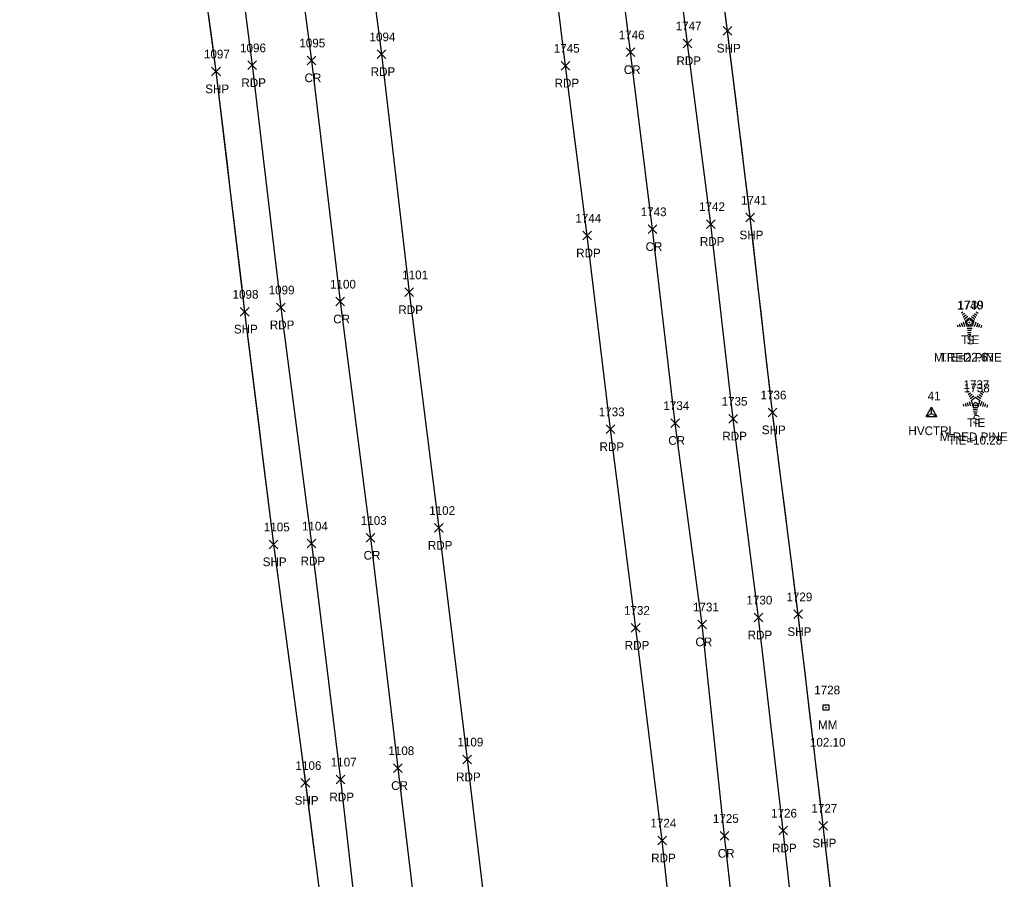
# Model space of a CAD drawing. Extents: x 1472022 to 1479249, y 777216 to 786527.
# Drawn here: x 1473815.7 to 1474042.7, y 782126.8 to 782324.3 of the extents above; entities that cross this region are included whole.
import ezdxf

# ---------------------------------------------------------------- set-up
doc = ezdxf.new("R2010")
doc.units = 0
for name, color, linetype in [('C_A', 7, 'Continuous'), ('C_C', 7, 'Continuous'), ('C_I', 7, 'Continuous'), ('CBP', 7, 'Continuous'), ('CPSM', 7, 'Continuous'), ('L_A', 7, 'Continuous'), ('L_C', 7, 'Continuous'), ('L_I', 7, 'Continuous'), ('LSOGP', 7, 'Continuous'), ('LTC', 7, 'Continuous'), ('P_A', 7, 'Continuous'), ('P_I', 7, 'Continuous'), ('P_TIC', 7, 'Continuous'), ('PET', 7, 'Continuous'), ('PRC', 7, 'Continuous'), ('PSP', 7, 'Continuous'), ('S_A', 7, 'Continuous'), ('S_C', 7, 'Continuous'), ('S_I', 7, 'Continuous'), ('SRM', 7, 'Continuous')]:
    doc.layers.add(name, color=color, linetype=linetype)

msp = doc.modelspace()

# ---------------------------------------------------------------- linework, layer by layer
at = {"layer": 'CBP'}
for centre, radius in [((1474034.07, 782254.77), 0.625), ((1474034.07, 782254.77), 0.0833), ((1474035.44, 782235.7), 0.625), ((1474035.44, 782235.7), 0.0833)]:
    msp.add_circle(centre, radius, dxfattribs=at)
at = {"layer": 'CPSM'}
for p, q in [((1474024.07, 782233.14), (1474025.32, 782235.3)), ((1474024.07, 782233.14), (1474025.32, 782233.86)), ((1474026.57, 782233.14), (1474025.32, 782235.3)), ((1474025.32, 782233.86), (1474025.32, 782235.3)), ((1474025.32, 782233.86), (1474025.32, 782233.86)), ((1474025.32, 782233.86), (1474026.57, 782233.14)), ((1474024.07, 782233.14), (1474026.57, 782233.14))]:
    msp.add_line(p, q, dxfattribs=at)
at = {"layer": 'LSOGP'}
for points in [[(1474002.29, 782123.21), (1474001.66, 782128.51), (1474001.04, 782133.8), (1474000.42, 782139.1), (1473999.7, 782145.17), (1473998.98, 782151.25), (1473998.26, 782157.32), (1473997.54, 782163.39), (1473996.82, 782169.47), (1473996.11, 782175.54), (1473995.39, 782181.61), (1473994.67, 782187.68), (1473993.93, 782193.48), (1473993.19, 782199.28), (1473992.46, 782205.08), (1473991.72, 782210.88), (1473990.98, 782216.68), (1473990.25, 782222.48), (1473989.51, 782228.28), (1473988.77, 782234.07), (1473988.13, 782239.67), (1473987.49, 782245.27), (1473986.85, 782250.87), (1473986.21, 782256.46), (1473985.57, 782262.06), (1473984.93, 782267.66), (1473984.29, 782273.25), (1473983.65, 782278.85), (1473982.99, 782284.22), (1473982.34, 782289.58), (1473981.69, 782294.95), (1473981.03, 782300.31), (1473980.38, 782305.68), (1473979.73, 782311.05), (1473979.07, 782316.41), (1473978.42, 782321.78), (1473977.15, 782331.6)], [(1473859.03, 782325.7), (1473859.93, 782319.06), (1473860.83, 782312.43), (1473861.65, 782305.53), (1473862.47, 782298.62), (1473863.3, 782291.72), (1473864.12, 782284.82), (1473864.94, 782277.92), (1473865.77, 782271.02), (1473866.59, 782264.12), (1473867.42, 782257.22), (1473868.24, 782250.54), (1473869.07, 782243.85), (1473869.9, 782237.17), (1473870.72, 782230.48), (1473871.55, 782223.8), (1473872.38, 782217.11), (1473873.21, 782210.43), (1473874.03, 782203.74), (1473874.95, 782196.89), (1473875.87, 782190.04), (1473876.79, 782183.18), (1473877.7, 782176.33), (1473878.62, 782169.48), (1473879.54, 782162.63), (1473880.46, 782155.77), (1473882.24, 782142.14), (1473883.11, 782135.37), (1473883.98, 782128.59), (1473884.85, 782121.82)]]:
    msp.add_lwpolyline(points, dxfattribs=at)
at = {"layer": 'LTC'}
for p, q in [((1474032.2, 782256.93), (1474032.55, 782257.19)), ((1474032.41, 782256.47), (1474032.94, 782256.85)), ((1474032.62, 782256), (1474033.32, 782256.51)), ((1474032.83, 782255.53), (1474033.7, 782256.17)), ((1474034.85, 782256.47), (1474035.53, 782255.98)), ((1474035.22, 782256.82), (1474035.77, 782256.42)), ((1474035.6, 782257.17), (1474036.01, 782256.87)), ((1474031.23, 782254.21), (1474031.38, 782253.74)), ((1474031.68, 782254.43), (1474031.9, 782253.77)), ((1474032.14, 782254.64), (1474032.41, 782253.81)), ((1474032.6, 782254.86), (1474032.93, 782253.84)), ((1474033.05, 782255.08), (1474034.06, 782255.81)), ((1474033.05, 782255.08), (1474033.44, 782253.89)), ((1474034.67, 782253.89), (1474033.44, 782253.89)), ((1474034.06, 782255.81), (1474035.06, 782255.09)), ((1474034.48, 782256.13), (1474035.29, 782255.54)), ((1474035.06, 782255.09), (1474034.67, 782253.89)), ((1474035.5, 782254.82), (1474035.16, 782253.78)), ((1474035.94, 782254.57), (1474035.65, 782253.68)), ((1474036.39, 782254.32), (1474036.15, 782253.59)), ((1474036.83, 782254.07), (1474036.64, 782253.49)), ((1474034.63, 782253.39), (1474033.48, 782253.39)), ((1474034.55, 782252.89), (1474033.56, 782252.89)), ((1474034.46, 782252.39), (1474033.63, 782252.39)), ((1474034.38, 782251.89), (1474033.7, 782251.89)), ((1474033.57, 782238.68), (1474033.92, 782238.94)), ((1474033.78, 782238.22), (1474034.3, 782238.6)), ((1474033.99, 782237.75), (1474034.69, 782238.26)), ((1474036.22, 782238.22), (1474036.9, 782237.73)), ((1474036.59, 782238.57), (1474037.14, 782238.17)), ((1474036.96, 782238.92), (1474037.38, 782238.62)), ((1474032.6, 782235.96), (1474032.75, 782235.49)), ((1474033.05, 782236.18), (1474033.27, 782235.52)), ((1474033.51, 782236.39), (1474033.78, 782235.56)), ((1474033.96, 782236.61), (1474034.3, 782235.59)), ((1474034.19, 782237.28), (1474035.07, 782237.92)), ((1474034.42, 782236.83), (1474035.43, 782237.56)), ((1474034.42, 782236.83), (1474034.81, 782235.64)), ((1474035.43, 782237.56), (1474036.43, 782236.84)), ((1474035.85, 782237.88), (1474036.66, 782237.29)), ((1474036.43, 782236.84), (1474036.04, 782235.64)), ((1474036.87, 782236.57), (1474036.53, 782235.53)), ((1474037.31, 782236.32), (1474037.02, 782235.43)), ((1474037.75, 782236.07), (1474037.52, 782235.34)), ((1474038.2, 782235.82), (1474038.01, 782235.24)), ((1474036.04, 782235.64), (1474034.81, 782235.64)), ((1474036, 782235.14), (1474034.85, 782235.14)), ((1474035.91, 782234.64), (1474034.93, 782234.64)), ((1474035.83, 782234.14), (1474035, 782234.14)), ((1474035.75, 782233.64), (1474035.07, 782233.64))]:
    msp.add_line(p, q, dxfattribs=at)
at = {"layer": 'P_TIC'}
for points in [[(1473977.42, 782320.78), (1473979.42, 782322.78)], [(1473979.42, 782320.78), (1473977.42, 782322.78)], [(1473968.2, 782317.89), (1473970.2, 782319.89)], [(1473970.2, 782317.89), (1473968.2, 782319.89)], [(1473955.15, 782315.84), (1473957.15, 782317.84)], [(1473957.15, 782315.84), (1473955.15, 782317.84)], [(1473881.76, 782313.97), (1473883.76, 782315.97)], [(1473883.76, 782313.97), (1473881.76, 782315.97)], [(1473897.9, 782315.38), (1473899.9, 782317.38)], [(1473899.9, 782315.38), (1473897.9, 782317.38)], [(1473859.83, 782311.43), (1473861.83, 782313.43)], [(1473861.83, 782311.43), (1473859.83, 782313.43)], [(1473868.18, 782312.85), (1473870.18, 782314.85)], [(1473870.18, 782312.85), (1473868.18, 782314.85)], [(1473940.19, 782312.76), (1473942.19, 782314.76)], [(1473942.19, 782312.76), (1473940.19, 782314.76)], [(1473982.65, 782277.85), (1473984.65, 782279.85)], [(1473984.65, 782277.85), (1473982.65, 782279.85)], [(1473960.16, 782275.18), (1473962.16, 782277.18)], [(1473962.16, 782275.18), (1473960.16, 782277.18)], [(1473973.58, 782276.36), (1473975.58, 782278.36)], [(1473975.58, 782276.36), (1473973.58, 782278.36)], [(1473945.14, 782273.71), (1473947.14, 782275.71)], [(1473947.14, 782273.71), (1473945.14, 782275.71)], [(1473904.27, 782260.68), (1473906.27, 782262.68)], [(1473906.27, 782260.68), (1473904.27, 782262.68)], [(1473874.71, 782257.2), (1473876.71, 782259.2)], [(1473876.71, 782257.2), (1473874.71, 782259.2)], [(1473888.35, 782258.54), (1473890.35, 782260.54)], [(1473890.35, 782258.54), (1473888.35, 782260.54)], [(1473866.42, 782256.22), (1473868.42, 782258.22)], [(1473868.42, 782256.22), (1473866.42, 782258.22)], [(1473978.75, 782231.63), (1473980.75, 782233.63)], [(1473980.75, 782231.63), (1473978.75, 782233.63)], [(1473987.77, 782233.07), (1473989.77, 782235.07)], [(1473989.77, 782233.07), (1473987.77, 782235.07)], [(1473950.51, 782229.2), (1473952.51, 782231.2)], [(1473952.51, 782229.2), (1473950.51, 782231.2)], [(1473965.37, 782230.63), (1473967.37, 782232.63)], [(1473967.37, 782230.63), (1473965.37, 782232.63)], [(1473911.06, 782206.53), (1473913.06, 782208.53)], [(1473913.06, 782206.53), (1473911.06, 782208.53)], [(1473895.33, 782204.24), (1473897.33, 782206.24)], [(1473897.33, 782204.24), (1473895.33, 782206.24)], [(1473873.03, 782202.74), (1473875.03, 782204.74)], [(1473875.03, 782202.74), (1473873.03, 782204.74)], [(1473881.8, 782202.94), (1473883.8, 782204.94)], [(1473883.8, 782202.94), (1473881.8, 782204.94)], [(1473993.67, 782186.68), (1473995.67, 782188.68)], [(1473995.67, 782186.68), (1473993.67, 782188.68)], [(1473971.62, 782184.34), (1473973.62, 782186.34)], [(1473973.62, 782184.34), (1473971.62, 782186.34)], [(1473984.56, 782185.94), (1473986.56, 782187.94)], [(1473986.56, 782185.94), (1473984.56, 782187.94)], [(1473956.31, 782183.57), (1473958.31, 782185.57)], [(1473958.31, 782183.57), (1473956.31, 782185.57)], [(1473917.55, 782153.32), (1473919.55, 782155.32)], [(1473919.55, 782153.32), (1473917.55, 782155.32)], [(1473901.66, 782151.32), (1473903.66, 782153.32)], [(1473903.66, 782151.32), (1473901.66, 782153.32)], [(1473880.37, 782147.92), (1473882.37, 782149.92)], [(1473882.37, 782147.92), (1473880.37, 782149.92)], [(1473888.42, 782148.71), (1473890.42, 782150.71)], [(1473890.42, 782148.71), (1473888.42, 782150.71)], [(1473990.19, 782136.97), (1473992.19, 782138.97)], [(1473992.19, 782136.97), (1473990.19, 782138.97)], [(1473999.42, 782138.1), (1474001.42, 782140.1)], [(1474001.42, 782138.1), (1473999.42, 782140.1)], [(1473962.4, 782134.69), (1473964.4, 782136.69)], [(1473964.4, 782134.69), (1473962.4, 782136.69)], [(1473976.75, 782135.74), (1473978.75, 782137.74)], [(1473978.75, 782135.74), (1473976.75, 782137.74)]]:
    msp.add_lwpolyline(points, dxfattribs=at)
at = {"layer": 'PET'}
for points in [[(1474013.69, 781892.18), (1474009.96, 781943.03), (1474006.04, 781995.15), (1474000.49, 782052.02), (1473996.08, 782094.84), (1473991.19, 782137.97), (1473985.56, 782186.94), (1473979.75, 782232.63), (1473974.58, 782277.36), (1473969.2, 782318.89), (1473964.03, 782360.94), (1473956.61, 782419.72), (1473949.82, 782474.29), (1473942.88, 782526.93), (1473938.67, 782561.99), (1473934.65, 782592.56), (1473928.69, 782642.75), (1473922.69, 782688.94)], [(1473985.44, 781889.72), (1473981.98, 781941.8), (1473978.08, 781993.88), (1473972.71, 782048.23), (1473968.17, 782091.71), (1473963.4, 782135.69), (1473957.31, 782184.57), (1473951.51, 782230.2), (1473946.14, 782274.71), (1473941.19, 782313.76), (1473936.4, 782352.51), (1473927.93, 782415.63), (1473921.17, 782470.8), (1473914.11, 782524.35), (1473909.99, 782558.8), (1473906.05, 782589.71), (1473900.14, 782638.94), (1473894.25, 782685.56)], [(1473853.26, 782678.74), (1473862.81, 782601.91), (1473872.29, 782529.45), (1473878.87, 782478.11), (1473885.04, 782425.74), (1473891.89, 782369.8), (1473898.9, 782316.38), (1473905.27, 782261.68), (1473912.06, 782207.53), (1473918.55, 782154.32), (1473925.4, 782097.13), (1473931.1, 782043.01), (1473936.65, 781984.46), (1473941.26, 781927.31)], [(1473823.32, 782677.22), (1473833.33, 782599.61), (1473842.53, 782526.83), (1473848.75, 782473.74), (1473855.58, 782422.3), (1473862.39, 782366.21), (1473869.18, 782313.85), (1473875.71, 782258.2), (1473882.8, 782203.94), (1473889.42, 782149.71), (1473895.62, 782095.5), (1473901.27, 782040.19), (1473906.73, 781982.64), (1473911.24, 781925.62)]]:
    msp.add_lwpolyline(points, dxfattribs=at)
at = {"layer": 'PRC'}
for points in [[(1474000.48, 781890.51), (1473996.64, 781942.33), (1473992.75, 781993.73), (1473987.41, 782050.11), (1473982.69, 782092.94), (1473977.75, 782136.74), (1473972.62, 782185.34), (1473966.37, 782231.63), (1473961.16, 782276.18), (1473956.15, 782316.84), (1473951.46, 782354.9), (1473943.69, 782417.69), (1473936.64, 782472.53), (1473929.75, 782525.36), (1473925.27, 782560.63), (1473921.44, 782591.12), (1473915.37, 782640.6), (1473907.8, 782687.43)], [(1473836.1, 782681.15), (1473846.69, 782601.05), (1473856.08, 782526.86), (1473862.37, 782475.58), (1473868.64, 782425.17), (1473875.77, 782367.97), (1473882.76, 782314.97), (1473889.35, 782259.54), (1473896.33, 782205.24), (1473902.66, 782152.32), (1473909.3, 782096.74), (1473914.5, 782041.75), (1473920.36, 781983.62), (1473924.52, 781926.3)]]:
    msp.add_lwpolyline(points, dxfattribs=at)
at = {"layer": 'PSP'}
for points in [[(1474023.21, 781893.51), (1474019.96, 781943.82), (1474015.51, 781996.53), (1474014.23, 782008.91), (1474009.76, 782053.22), (1474005.41, 782096.71), (1474000.42, 782139.1), (1473994.67, 782187.68), (1473988.77, 782234.07), (1473983.65, 782278.85), (1473978.42, 782321.78), (1473973.33, 782361.06), (1473966.01, 782421.25), (1473959.18, 782474.93), (1473952.46, 782528.67), (1473948.21, 782563.48), (1473944.2, 782593.52), (1473937.62, 782642.8), (1473931.59, 782689.38)], [(1473815.72, 782675.07), (1473824.83, 782598.85), (1473833.44, 782525.48), (1473840.22, 782472.27), (1473847.17, 782419.46), (1473853.65, 782365.53), (1473860.83, 782312.43), (1473867.42, 782257.22), (1473874.03, 782203.74), (1473881.37, 782148.92), (1473888.32, 782094.71), (1473894.18, 782041.01), (1473899.44, 781982.31), (1473904.16, 781925.33)]]:
    msp.add_lwpolyline(points, dxfattribs=at)
at = {"layer": 'SRM'}
msp.add_lwpolyline([(1474000.43, 782166.91), (1474001.68, 782166.91), (1474001.68, 782165.66), (1474000.43, 782165.66)], close=True, dxfattribs=at)
msp.add_circle((1474001.05, 782166.28), 0.0833, dxfattribs=at)

# ---------------------------------------------------------------- texts
at = {"layer": 'C_A'}
for s, p in [('TIE', (1474032.15, 782249.77)), ('TIE', (1474033.52, 782230.7)), ('HVCTRL', (1474020.02, 782228.86))]:
    msp.add_text(s, height=2, dxfattribs=at).set_placement(p)
at = {"layer": 'C_C'}
for s, p in [('TIE=22.67', (1474027.25, 782245.77)), ('TIE=10.28', (1474029.16, 782226.7))]:
    msp.add_text(s, height=2, dxfattribs=at).set_placement(p)
at = {"layer": 'C_I'}
for s, p in [('1739', (1474031.37, 782257.77)), ('1738', (1474032.75, 782238.7)), ('41', (1474024.42, 782236.86))]:
    msp.add_text(s, height=2, dxfattribs=at).set_placement(p)
at = {"layer": 'L_A'}
for p in [(1474033.39, 782249.72), (1474034.76, 782231.47)]:
    msp.add_text('S', height=2, dxfattribs=at).set_placement(p)
at = {"layer": 'L_C'}
for p in [(1474025.88, 782245.72), (1474027.24, 782227.47)]:
    msp.add_text('M.RED PINE', height=2, dxfattribs=at).set_placement(p)
at = {"layer": 'L_I'}
for s, p in [('1740', (1474031.22, 782257.72)), ('1737', (1474032.68, 782239.47))]:
    msp.add_text(s, height=2, dxfattribs=at).set_placement(p)
at = {"layer": 'LTC'}
for p in [(1474033.94, 782254.83), (1474035.31, 782236.58)]:
    msp.add_text('.', height=1.04, rotation=270, dxfattribs=at).set_placement(p)
at = {"layer": 'P_A'}
for s, p in [('SHP', (1473975.96, 782316.78)), ('RDP', (1473966.69, 782313.89)), ('RDP', (1473896.39, 782311.38)), ('CR', (1473954.59, 782311.84)), ('RDP', (1473866.67, 782308.85)), ('CR', (1473881.19, 782309.97)), ('RDP', (1473938.67, 782308.76)), ('SHP', (1473858.36, 782307.43)), ('RDP', (1473972.07, 782272.36)), ('SHP', (1473981.18, 782273.85)), ('CR', (1473959.59, 782271.18)), ('RDP', (1473943.63, 782269.71)), ('RDP', (1473902.76, 782256.68)), ('CR', (1473887.78, 782254.54)), ('SHP', (1473864.95, 782252.22)), ('RDP', (1473873.2, 782253.2)), ('RDP', (1473977.24, 782227.63)), ('SHP', (1473986.31, 782229.07)), ('RDP', (1473949, 782225.2)), ('CR', (1473964.81, 782226.63)), ('RDP', (1473909.54, 782202.53)), ('CR', (1473894.76, 782200.24)), ('SHP', (1473871.57, 782198.74)), ('RDP', (1473880.29, 782198.94)), ('RDP', (1473983.05, 782181.94)), ('SHP', (1473992.2, 782182.68)), ('RDP', (1473954.8, 782179.57)), ('CR', (1473971.05, 782180.34)), ('RDP', (1473916.03, 782149.32)), ('CR', (1473901.1, 782147.32)), ('SHP', (1473878.91, 782143.92)), ('RDP', (1473886.91, 782144.71)), ('SHP', (1473997.95, 782134.1)), ('CR', (1473976.18, 782131.74)), ('RDP', (1473988.68, 782132.97)), ('RDP', (1473960.88, 782130.69))]:
    msp.add_text(s, height=2, dxfattribs=at).set_placement(p)
at = {"layer": 'P_I'}
for s, p in [('1747', (1473966.51, 782321.89)), ('1095', (1473879.99, 782317.97)), ('1094', (1473896.13, 782319.38)), ('1746', (1473953.41, 782319.84)), ('1097', (1473858.06, 782315.43)), ('1096', (1473866.36, 782316.85)), ('1745', (1473938.49, 782316.76)), ('1741', (1473981.52, 782281.85)), ('1743', (1473958.46, 782279.18)), ('1742', (1473971.89, 782280.36)), ('1744', (1473943.45, 782277.71)), ('1101', (1473903.64, 782264.68)), ('1099', (1473872.93, 782261.2)), ('1100', (1473887.05, 782262.54)), ('1098', (1473864.64, 782260.22)), ('1736', (1473986.02, 782237.07)), ('1734', (1473963.68, 782234.63)), ('1735', (1473977.06, 782235.63)), ('1733', (1473948.82, 782233.2)), ('1102', (1473909.85, 782210.53)), ('1105', (1473871.83, 782206.74)), ('1104', (1473880.6, 782206.94)), ('1103', (1473894.12, 782208.24)), ('1729', (1473991.97, 782190.68)), ('1731', (1473970.49, 782188.34)), ('1730', (1473982.78, 782189.94)), ('1732', (1473954.62, 782187.57)), ('1109', (1473916.33, 782157.32)), ('1108', (1473900.46, 782155.32)), ('1107', (1473887.21, 782152.71)), ('1106', (1473879.11, 782151.92)), ('1726', (1473988.44, 782140.97)), ('1727', (1473997.72, 782142.1)), ('1724', (1473960.7, 782138.69)), ('1725', (1473975.06, 782139.74))]:
    msp.add_text(s, height=2, dxfattribs=at).set_placement(p)
at = {"layer": 'S_A'}
msp.add_text('MM', height=2, dxfattribs=at).set_placement((1473999.24, 782161.28))
at = {"layer": 'S_C'}
msp.add_text('102.10', height=2, dxfattribs=at).set_placement((1473997.37, 782157.28))
at = {"layer": 'S_I'}
msp.add_text('1728', height=2, dxfattribs=at).set_placement((1473998.36, 782169.28))

doc.saveas('drawing.dxf')
